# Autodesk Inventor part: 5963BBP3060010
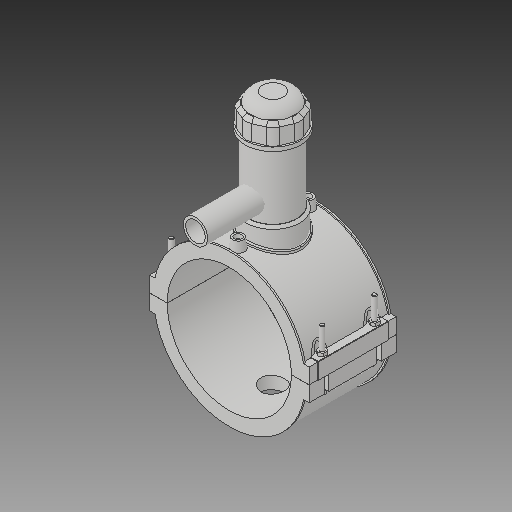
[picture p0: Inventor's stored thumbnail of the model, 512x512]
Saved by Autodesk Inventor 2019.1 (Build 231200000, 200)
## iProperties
Created: 2017-07
Part Number: 5963BBP3060010
Material: Generic
Description: PLASSON TAPPING SADDLE 6''IPS x 1''IPS
Document SubType Name: Modeling
Designer: KIM
Density: 1 g/cm^3
Appearance: Default
Author: KIM
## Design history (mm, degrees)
derived "5963BBP_5963BUP.ipt"
feature "Solid1::5963BBP_5963BUP.ipt"
feature "Solid2::5963BBP_5963BUP.ipt"
feature "Solid3::5963BBP_5963BUP.ipt"
tag "TaggingFeature1"
body "Solid1"
body "Solid2"
body "Solid3"
other parameters: "d0" = 168, "d2" = 215.9, "d3" = 42, "d4" = 118.11, "d5" = 0, "d6" = 0.1, "d8" = 0, "d19" = 6, "d20" = 6, "d21" = 70.866, "d23" = 0, "d24" = 35.433, "d26" = 0, "d27" = 3, "d28" = 3, "d29" = 3, "d30" = 56, "d31" = 6, "d32" = 0, "d33" = 0, "d34" = 0.6, "d40" = 104.832, "d41" = 75.6, "d43" = 0, "d45" = 0, "d47" = 171.666, "d70" = 15, "d72" = 0, "d73" = 6, "d75" = 5, "d76" = 0, "d77" = 8.4, "d78" = 114, "d79" = 15, "d80" = 47.244, "d82" = 5 deg, "d84" = 4, "d85" = 14, "d86" = 0, "d87" = 3, "d88" = 0, "d89" = 1, "d90" = 1, "d91" = 94.488, "d92" = 0, "d93" = 0.5, "d94" = 88.42105, "d96" = 205.632, "d97" = 2.3622, "d98" = 0, "d102" = 1.68, "d120" = 140 deg, "d121" = 24.228, "d122" = 20 deg, "d123" = 403.2, "d124" = 120.96, "d126" = 0, "d143" = 173.04, "d145" = 25.84615, "d149" = 2.52, "d150" = 28.43077, "d153" = 118.11, "d154" = 0, "d156" = 100.8, "d157" = 160 deg, "d159" = 6.72, "d161" = 2.52, "d162" = 70.866, "d163" = 0, "d164" = 84, "d167" = 16.8, "d168" = 98.34146, "d170" = 3.2805, "d172" = 0, "d173" = 1, "d175" = 84, "d176" = 20 deg, "d177" = 11.76, "d178" = 33.6, "d180" = 0, "d183" = 13.44, "d184" = 9.408, "d185" = 38.38575, "d186" = 38.38575, "d187" = 100.8, "d188" = 10.08, "d189" = 11.76, "d190" = 0, "d191" = 151.2, "d193" = 6.9984, "d194" = 4.13385, "d195" = 90 deg, "d197" = 0, "d199" = 0, "d200" = 16.8, "d202" = 0, "d203" = 177.038, "d204" = 71.82, "d205" = 52.92, "d206" = 64.26, "d207" = 132.7785, "d208" = 138.08964, "d209" = 164.64534, "d210" = 65.016, "d211" = 75.6, "d212" = 60.48, "d213" = 43.5366, "d216" = 0, "d217" = 16.8, "d218" = 16.8, "d219" = 3.36, "d222" = 168, "d224" = 0, "d225" = 65.024, "d226" = 33.3, "d227" = 26.64, "d228" = 104.902, "d230" = 5.04, "d_" = 168, "B_" = 215.9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
